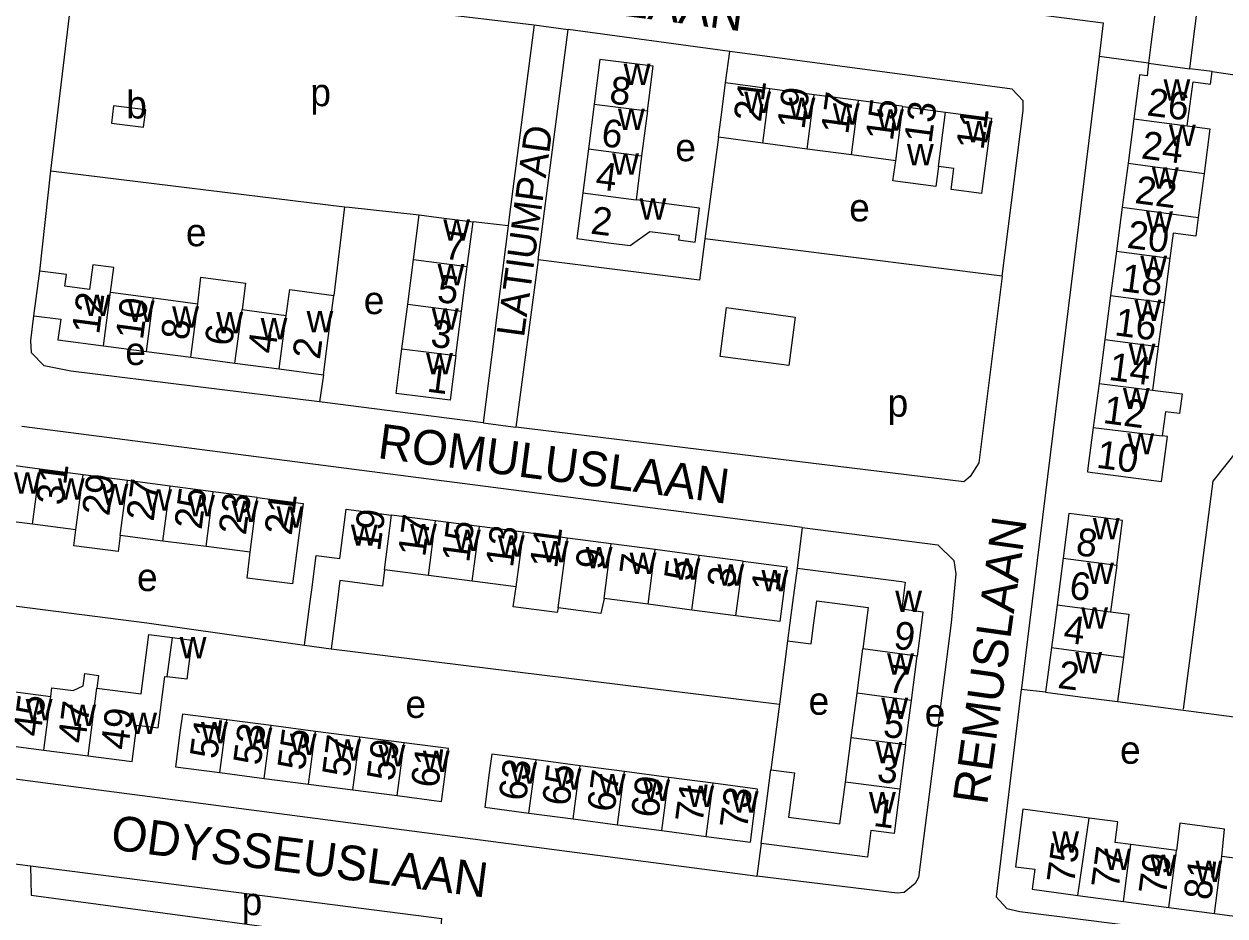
# Model space of a CAD drawing. Extents: x 161773 to 163836, y 384796 to 386521.
# Drawn here: x 162373.5 to 162546.6, y 386124.5 to 386253 of the extents above; entities that cross this region are included whole.
import ezdxf

# ---------------------------------------------------------------- set-up
doc = ezdxf.new("R2010")
doc.units = 0
for name, color, linetype in [('BLT_Basislijn', 7, 'Continuous'), ('BLT_Bebouwing', 7, 'Continuous'), ('BLT_Centroide', 7, 'Continuous'), ('BLT_Huisnummer', 7, 'Continuous'), ('BLT_Huisnummer_ tussenligend', 7, 'Continuous'), ('BLT_Onderverdeling_panden', 7, 'Continuous'), ('BLT_Straatnaam', 7, 'Continuous'), ('BLT_Straatnaam_verkleind', 7, 'Continuous')]:
    doc.layers.add(name, color=color, linetype=linetype)

msp = doc.modelspace()

# ---------------------------------------------------------------- linework, layer by layer
at = {"layer": 'BLT_Basislijn'}
for p, q in [((162447.05, 386252.85), (162451.93, 386252.19)), ((162447.64, 386218.99), (162451.93, 386252.19)), ((162475.24, 386249.02), (162451.93, 386252.19)), ((162474.65, 386244.47), (162475.24, 386249.02)), ((162535.6, 386247.3), (162528.49, 386248.27)), ((162544.76, 386246.1), (162549.69, 386245.41)), ((162473.62, 386236.64), (162471.67, 386222.02)), ((162377.35, 386231.82), (162419.71, 386226.64)), ((162419.71, 386226.64), (162418.17, 386213.85)), ((162443.28, 386223.88), (162438.24, 386224.45)), ((162443.28, 386223.88), (162439.7, 386195.48)), ((162514.5, 386216.65), (162471.67, 386222.02)), ((162447.64, 386218.99), (162444.41, 386194.89)), ((162416.67, 386202.42), (162416.09, 386198.52)), ((162439.7, 386195.48), (162444.41, 386194.89)), ((162485.66, 386180.43), (162484.94, 386174.58)), ((162417.76, 386162.95), (162482.39, 386154.98)), ((162483.57, 386164.09), (162482.39, 386154.98)), ((162520.78, 386156.68), (162517.27, 386157.06)), ((162482.39, 386154.98), (162481.17, 386145.49)), ((162531.15, 386155.33), (162553.03, 386152.48)), ((162479.79, 386134.91), (162479.16, 386130.19)), ((162369.94, 386132.24), (162374.45, 386131.66)), ((162374.45, 386131.66), (162433.75, 386124.08))]:
    msp.add_line(p, q, dxfattribs=at)
for points in [[(162407.16, 386268.86), (162529.09, 386253.11), (162528.49, 386248.27)], [(162377.35, 386231.82), (162380.53, 386258.21), (162382.19, 386260.12), (162383.56, 386260.45), (162447.05, 386252.85)], [(162447.05, 386252.85), (162443.49, 386225.52), (162443.28, 386223.88)], [(162514.5, 386216.65), (162517.54, 386240.51), (162517.56, 386241.89), (162515.97, 386243.59), (162475.24, 386249.02)], [(162528.49, 386248.27), (162518.46, 386166.67), (162517.3, 386157.29), (162517.27, 386157.06)], [(162540.64, 386154.24), (162544.92, 386187.1), (162550.17, 386193.67), (162555.68, 386244.61)], [(162375.77, 386217.37), (162377.35, 386231.82)], [(162419.71, 386226.64), (162420.4, 386226.55), (162430.47, 386225.45)], [(162471.67, 386222.02), (162470.87, 386216.06), (162447.64, 386218.99)], [(162514.5, 386216.65), (162511.13, 386189.75), (162509.9, 386187.78), (162508.97, 386186.98), (162444.41, 386194.89)], [(162416.09, 386198.52), (162380.25, 386202.96), (162376.4, 386203.69), (162374.56, 386205.6), (162374.49, 386207.35), (162374.92, 386210.93)], [(162439.7, 386195.48), (162416.85, 386198.43), (162416.09, 386198.52)], [(162485.66, 386180.43), (162484.59, 386180.57), (162373.17, 386194.96)], [(162485.66, 386180.43), (162505.24, 386177.91), (162507.54, 386175.68), (162507.82, 386173.74), (162507.16, 386166.67), (162502.44, 386130), (162501.96, 386129.11), (162500.37, 386127.81), (162499.36, 386127.73), (162479.16, 386130.19)], [(162349.54, 386172.01), (162391.2, 386166.67), (162413.94, 386163.45)], [(162517.27, 386157.06), (162513.65, 386127.2), (162515.18, 386125.55), (162517.05, 386125.1), (162553.21, 386120.54), (162557.19, 386120.68), (162558.62, 386122.04), (162567.26, 386150.66)], [(162346.48, 386147.55), (162478.17, 386130.31), (162479.16, 386130.19)], [(162374.45, 386131.66), (162374.52, 386127.46), (162431.78, 386119.74), (162433.18, 386119.69), (162433.34, 386119.94), (162433.75, 386124.08)]]:
    msp.add_lwpolyline(points, dxfattribs=at)
msp.add_lwpolyline([(162474.78, 386212.11), (162484.69, 386210.73), (162483.77, 386203.75), (162473.86, 386205.07)], close=True, dxfattribs=at)
at = {"layer": 'BLT_Bebouwing'}
for p, q in [((162481.04, 386243.63), (162474.65, 386244.47)), ((162487.43, 386242.78), (162481.04, 386243.63)), ((162493.81, 386241.94), (162487.43, 386242.78)), ((162455.69, 386241.42), (162454.86, 386234.96)), ((162500.2, 386241.09), (162506.35, 386240.28)), ((162463.38, 386240.43), (162462.54, 386233.97)), ((162533.49, 386239.28), (162532.66, 386232.93)), ((162480, 386235.79), (162473.62, 386236.64)), ((162486.39, 386234.95), (162480, 386235.79)), ((162454.86, 386234.96), (162454.04, 386228.63)), ((162462.54, 386233.97), (162461.73, 386227.64)), ((162492.78, 386234.1), (162486.39, 386234.95)), ((162499.16, 386233.26), (162492.78, 386234.1)), ((162532.66, 386232.93), (162531.82, 386226.58)), ((162543.63, 386231.44), (162542.76, 386225.07)), ((162429.64, 386219.02), (162430.47, 386225.45)), ((162531.82, 386226.58), (162530.98, 386220.22)), ((162437.41, 386218.03), (162438.24, 386224.45)), ((162530.98, 386220.22), (162530.14, 386213.87)), ((162428.82, 386212.6), (162429.64, 386219.02)), ((162436.59, 386211.6), (162437.41, 386218.03)), ((162538.69, 386219.21), (162537.85, 386212.85)), ((162374.92, 386210.93), (162375.77, 386217.37)), ((162385.99, 386214.31), (162392.17, 386213.49)), ((162392.17, 386213.49), (162398.55, 386212.65)), ((162530.14, 386213.87), (162529.31, 386207.51)), ((162537.85, 386212.85), (162537.02, 386206.5)), ((162404.93, 386211.81), (162411.31, 386210.97)), ((162427.99, 386206.18), (162428.82, 386212.6)), ((162435.76, 386205.18), (162436.59, 386211.6)), ((162384.98, 386206.6), (162391.15, 386205.78)), ((162529.31, 386207.51), (162528.47, 386201.16)), ((162537.02, 386206.5), (162536.19, 386200.22)), ((162391.15, 386205.78), (162397.53, 386204.94)), ((162397.53, 386204.94), (162403.91, 386204.1)), ((162403.91, 386204.1), (162410.29, 386203.26)), ((162410.29, 386203.26), (162416.67, 386202.42)), ((162528.47, 386201.16), (162527.63, 386194.81)), ((162375.77, 386188.82), (162369.41, 386189.65)), ((162382.02, 386188), (162375.77, 386188.82)), ((162388.4, 386187.17), (162382.02, 386188)), ((162394.57, 386186.37), (162388.4, 386187.17)), ((162400.79, 386185.56), (162394.57, 386186.37)), ((162407.13, 386184.73), (162400.79, 386185.56)), ((162374.73, 386180.89), (162368.37, 386181.71)), ((162432.83, 386181.39), (162426.5, 386182.22)), ((162380.98, 386180.09), (162374.73, 386180.89)), ((162439.16, 386180.56), (162432.83, 386181.39)), ((162445.5, 386179.73), (162439.16, 386180.56)), ((162393.53, 386178.47), (162387.37, 386179.27)), ((162399.75, 386177.67), (162393.53, 386178.47)), ((162451.83, 386178.9), (162445.5, 386179.73)), ((162458.16, 386178.07), (162451.83, 386178.9)), ((162406.12, 386176.85), (162399.75, 386177.67)), ((162464.49, 386177.24), (162458.16, 386178.07)), ((162470.82, 386176.41), (162464.49, 386177.24)), ((162477.16, 386175.58), (162470.82, 386176.41)), ((162523.3, 386176.01), (162522.42, 386169.28)), ((162531.02, 386175.01), (162530.14, 386168.27)), ((162431.8, 386173.51), (162425.47, 386174.34)), ((162438.13, 386172.68), (162431.8, 386173.51)), ((162444.46, 386171.85), (162438.13, 386172.68)), ((162463.46, 386169.36), (162457.13, 386170.19)), ((162469.79, 386168.53), (162463.46, 386169.36)), ((162476.12, 386167.7), (162469.79, 386168.53)), ((162413.94, 386163.45), (162417.76, 386162.95)), ((162493.59, 386156.53), (162494.42, 386162.92)), ((162521.62, 386163.12), (162520.78, 386156.68)), ((162501.42, 386155.51), (162502.25, 386161.9)), ((162531.99, 386161.73), (162531.15, 386155.33)), ((162371.15, 386156.89), (162377.35, 386156.08)), ((162492.76, 386150.14), (162493.59, 386156.53)), ((162500.59, 386149.12), (162501.42, 386155.51)), ((162402.73, 386152.71), (162396.33, 386153.54)), ((162409.12, 386151.88), (162402.73, 386152.71)), ((162415.51, 386151.05), (162409.12, 386151.88)), ((162421.9, 386150.23), (162415.51, 386151.05)), ((162370.14, 386149.17), (162376.34, 386148.36)), ((162428.3, 386149.4), (162421.9, 386150.23)), ((162491.92, 386143.75), (162492.76, 386150.14)), ((162376.34, 386148.36), (162382.73, 386147.53)), ((162453.69, 386146.09), (162447.31, 386146.93)), ((162460.08, 386145.25), (162453.69, 386146.09)), ((162401.74, 386145.1), (162408.14, 386144.27)), ((162408.14, 386144.27), (162414.53, 386143.45)), ((162466.46, 386144.41), (162460.08, 386145.25)), ((162472.84, 386143.57), (162466.46, 386144.41)), ((162414.53, 386143.45), (162420.92, 386142.62)), ((162420.92, 386142.62), (162427.31, 386141.79)), ((162446.3, 386139.27), (162452.69, 386138.43)), ((162452.69, 386138.43), (162459.07, 386137.59)), ((162459.07, 386137.59), (162465.45, 386136.75)), ((162465.45, 386136.75), (162471.83, 386135.91)), ((162539.63, 386133.89), (162533.07, 386134.76)), ((162525.42, 386127.42), (162531.98, 386126.55)), ((162531.98, 386126.55), (162538.55, 386125.69)), ((162538.55, 386125.69), (162545.11, 386124.82))]:
    msp.add_line(p, q, dxfattribs=at)
for points in [[(162541.54, 386246.52), (162541.98, 386250), (162544.33, 386268.51), (162539.75, 386269.09)], [(162536.59, 386255.14), (162535.94, 386250), (162535.6, 386247.3)], [(162463.38, 386240.43), (162463.57, 386241.92), (162464.21, 386246.88), (162456.53, 386247.87), (162455.69, 386241.42)], [(162535.6, 386247.3), (162535.39, 386245.5), (162534.33, 386245.64), (162534.27, 386245.14), (162533.49, 386239.28)], [(162541.2, 386238.27), (162542.04, 386244.62), (162544.52, 386244.29), (162544.76, 386246.1)], [(162544.76, 386246.1), (162541.54, 386246.52)], [(162473.62, 386236.64), (162474, 386239.52), (162474.65, 386244.47)], [(162390.75, 386238.11), (162391.06, 386240.61), (162386.42, 386241.19), (162386.11, 386238.69), (162390.75, 386238.11)], [(162500.2, 386241.09), (162500, 386241.12), (162493.81, 386241.94)], [(162506.35, 386240.28), (162512.97, 386239.4), (162511.54, 386228.52), (162507.15, 386229.1), (162507.56, 386232.15), (162505.32, 386232.44)], [(162541.2, 386238.27), (162544.43, 386237.86), (162543.63, 386231.44)], [(162505.32, 386232.44), (162504.94, 386229.57), (162498.74, 386230.37), (162499.16, 386233.26)], [(162454.04, 386228.63), (162453.19, 386222.04), (162458.15, 386221.4), (162460.88, 386221.05), (162463.71, 386223.07), (162467.95, 386222.52), (162467.86, 386221.87), (162470.27, 386221.55), (162470.9, 386226.45), (162461.73, 386227.64)], [(162430.47, 386225.45), (162433.28, 386225.09), (162438.24, 386224.45)], [(162542.76, 386225.07), (162542.41, 386222.41), (162539.17, 386222.84), (162538.69, 386219.21)], [(162385.99, 386214.31), (162386.46, 386217.86), (162383.42, 386218.26), (162382.95, 386214.71), (162379.41, 386215.18), (162379.64, 386216.86), (162375.77, 386217.37)], [(162398.55, 386212.65), (162398.97, 386216.49), (162405.42, 386215.64), (162404.93, 386211.81)], [(162411.31, 386210.97), (162411.8, 386214.69), (162418.17, 386213.85)], [(162416.67, 386202.42), (162417.32, 386207.38), (162418.17, 386213.85)], [(162374.92, 386210.93), (162378.79, 386210.42), (162378.4, 386207.47), (162384.98, 386206.6)], [(162435.76, 386205.18), (162434.93, 386198.76), (162427.17, 386199.75), (162427.8, 386204.71), (162427.99, 386206.18)], [(162536.19, 386200.22), (162540.45, 386199.66), (162540.07, 386196.84), (162538.05, 386197.1), (162537.59, 386193.61)], [(162527.63, 386194.81), (162526.86, 386188.95), (162526.79, 386188.45), (162537.48, 386187.04), (162538.33, 386193.51), (162537.59, 386193.61)], [(162407.13, 386184.73), (162413.73, 386183.87), (162413.08, 386178.92), (162412.22, 386172.29), (162405.66, 386173.14), (162406.12, 386176.85)], [(162413.94, 386163.45), (162414.76, 386169.74), (162414.99, 386171.45), (162415.64, 386176.41), (162419.01, 386175.97), (162419.94, 386183.08), (162426.5, 386182.22)], [(162531.02, 386175.01), (162531.86, 386181.45), (162529.1, 386181.81), (162524.14, 386182.46), (162523.3, 386176.01)], [(162387.37, 386179.27), (162387.06, 386176.94), (162380.67, 386177.76), (162380.98, 386180.09)], [(162477.16, 386175.58), (162483.49, 386174.75), (162482.84, 386169.79), (162482.46, 386166.87), (162476.12, 386167.7)], [(162425.47, 386174.34), (162425.16, 386171.97), (162419.05, 386172.77), (162418.59, 386169.24), (162417.76, 386162.95)], [(162484.94, 386174.58), (162484.29, 386169.63), (162483.9, 386166.67), (162483.57, 386164.09)], [(162484.94, 386174.58), (162500, 386172.62), (162500.55, 386172.55), (162500.04, 386168.69), (162503.08, 386168.29), (162502.87, 386166.67), (162502.25, 386161.9)], [(162450.51, 386168.85), (162450.36, 386168.16), (162444.04, 386168.98), (162444.46, 386171.85)], [(162457.13, 386170.19), (162456.65, 386168.05), (162450.51, 386168.85)], [(162483.57, 386164.09), (162486.98, 386163.65), (162487.37, 386166.67), (162487.79, 386169.84), (162495.2, 386168.88), (162494.91, 386166.67), (162494.42, 386162.92)], [(162522.42, 386169.28), (162522.08, 386166.67), (162521.62, 386163.12)], [(162530.14, 386168.27), (162532.79, 386167.92), (162531.99, 386161.73)], [(162384.02, 386157.28), (162390.37, 386156.45), (162391.49, 386165.01), (162394.9, 386164.57)], [(162394.9, 386164.57), (162397.71, 386164.21), (162396.98, 386158.55), (162394.16, 386158.9)], [(162377.35, 386156.08), (162377.52, 386157.34), (162380.6, 386156.94), (162382.02, 386157.62), (162382.25, 386159.37), (162384.26, 386159.11), (162384.02, 386157.28)], [(162392.86, 386151.56), (162393.82, 386158.94), (162394.16, 386158.9)], [(162520.78, 386156.68), (162525.74, 386156.03), (162531.15, 386155.33)], [(162396.33, 386153.54), (162395.99, 386150.89), (162395.35, 386145.93), (162401.74, 386145.1)], [(162382.73, 386147.53), (162389.1, 386146.7), (162389.79, 386151.96), (162392.86, 386151.56)], [(162427.31, 386141.79), (162433.7, 386140.96), (162434.34, 386145.92), (162434.69, 386148.57), (162428.3, 386149.4)], [(162500.59, 386149.12), (162500, 386144.64), (162499.75, 386142.73)], [(162447.31, 386146.93), (162440.93, 386147.77), (162440.57, 386145.07), (162439.92, 386140.11), (162446.3, 386139.27)], [(162479.79, 386134.91), (162480.44, 386139.87), (162481.17, 386145.49)], [(162481.17, 386145.49), (162484.55, 386145.05), (162483.72, 386138.67), (162491.13, 386137.71), (162491.92, 386143.75)], [(162471.83, 386135.91), (162478.22, 386135.07), (162478.87, 386140.03), (162479.23, 386142.73), (162472.84, 386143.57)], [(162499.75, 386142.73), (162498.92, 386136.34), (162495.58, 386136.78), (162495.08, 386132.92), (162479.79, 386134.91)], [(162527.04, 386138.56), (162517.5, 386139.82), (162516.41, 386131.55), (162519.24, 386131.18), (162518.85, 386128.29), (162525.42, 386127.42)], [(162533.07, 386134.76), (162530.81, 386135.05), (162531.2, 386138.01), (162527.04, 386138.56)], [(162546.19, 386133.02), (162546.58, 386136.96), (162540.13, 386137.81), (162539.63, 386133.89)], [(162545.11, 386124.82), (162551.67, 386123.95), (162552.14, 386127.49), (162556.35, 386126.93), (162557.42, 386134.97), (162552.83, 386135.57), (162552.39, 386132.2), (162546.19, 386133.02)]]:
    msp.add_lwpolyline(points, dxfattribs=at)
at = {"layer": 'BLT_Onderverdeling_panden'}
for p, q in [((162480, 386235.79), (162481.04, 386243.63)), ((162486.39, 386234.95), (162487.43, 386242.78)), ((162455.69, 386241.42), (162463.38, 386240.43)), ((162492.78, 386234.1), (162493.81, 386241.94)), ((162499.16, 386233.26), (162500.2, 386241.09)), ((162505.32, 386232.44), (162506.35, 386240.28)), ((162533.49, 386239.28), (162541.2, 386238.27)), ((162454.86, 386234.96), (162462.54, 386233.97)), ((162532.66, 386232.93), (162543.63, 386231.44)), ((162454.04, 386228.63), (162461.73, 386227.64)), ((162531.82, 386226.58), (162542.76, 386225.07)), ((162530.98, 386220.22), (162538.69, 386219.21)), ((162429.64, 386219.02), (162437.41, 386218.03)), ((162384.98, 386206.6), (162385.99, 386214.31)), ((162391.15, 386205.78), (162392.17, 386213.49)), ((162530.14, 386213.87), (162537.85, 386212.85)), ((162397.53, 386204.94), (162398.55, 386212.65)), ((162403.91, 386204.1), (162404.93, 386211.81)), ((162428.82, 386212.6), (162436.59, 386211.6)), ((162410.29, 386203.26), (162411.31, 386210.97)), ((162427.99, 386206.18), (162435.76, 386205.18)), ((162529.31, 386207.51), (162537.02, 386206.5)), ((162528.47, 386201.16), (162536.19, 386200.22)), ((162527.63, 386194.81), (162537.59, 386193.61)), ((162374.73, 386180.89), (162375.77, 386188.82)), ((162380.98, 386180.09), (162382.02, 386188)), ((162387.37, 386179.27), (162388.4, 386187.17)), ((162393.53, 386178.47), (162394.57, 386186.37)), ((162399.75, 386177.67), (162400.79, 386185.56)), ((162406.12, 386176.85), (162407.13, 386184.73)), ((162425.47, 386174.34), (162426.5, 386182.22)), ((162431.8, 386173.51), (162432.83, 386181.39)), ((162438.13, 386172.68), (162439.16, 386180.56)), ((162444.46, 386171.85), (162445.5, 386179.73)), ((162450.51, 386168.85), (162451.83, 386178.9)), ((162457.13, 386170.19), (162458.16, 386178.07)), ((162463.46, 386169.36), (162464.49, 386177.24)), ((162469.79, 386168.53), (162470.82, 386176.41)), ((162476.12, 386167.7), (162477.16, 386175.58)), ((162523.3, 386176.01), (162531.02, 386175.01)), ((162522.42, 386169.28), (162530.14, 386168.27)), ((162394.16, 386158.9), (162394.9, 386164.57)), ((162502.25, 386161.9), (162494.42, 386162.92)), ((162521.62, 386163.12), (162531.99, 386161.73)), ((162376.34, 386148.36), (162377.35, 386156.08)), ((162382.73, 386147.53), (162384.02, 386157.28)), ((162501.42, 386155.51), (162493.59, 386156.53)), ((162401.74, 386145.1), (162402.73, 386152.71)), ((162408.14, 386144.27), (162409.12, 386151.88)), ((162414.53, 386143.45), (162415.51, 386151.05)), ((162420.92, 386142.62), (162421.9, 386150.23)), ((162427.31, 386141.79), (162428.3, 386149.4)), ((162500.59, 386149.12), (162492.76, 386150.14)), ((162446.3, 386139.27), (162447.31, 386146.93)), ((162452.69, 386138.43), (162453.69, 386146.09)), ((162459.07, 386137.59), (162460.08, 386145.25)), ((162465.45, 386136.75), (162466.46, 386144.41)), ((162471.83, 386135.91), (162472.84, 386143.57)), ((162499.75, 386142.73), (162491.92, 386143.75)), ((162525.42, 386127.42), (162527.04, 386138.56)), ((162531.98, 386126.55), (162533.07, 386134.76)), ((162538.55, 386125.69), (162539.63, 386133.89)), ((162545.11, 386124.82), (162546.19, 386133.02))]:
    msp.add_line(p, q, dxfattribs=at)
msp.add_lwpolyline([(162535.6, 386247.3), (162541.54, 386246.52)], dxfattribs=at)

# ---------------------------------------------------------------- texts
at = {"layer": 'BLT_Centroide'}
for s, p in [('w', (162459.95, 386244.16)), ('p', (162414.78, 386241.12)), ('w', (162537.77, 386241.94)), ('b', (162388.24, 386239.35)), ('w', (162477.33, 386240.14)), ('w', (162483.72, 386239.3)), ('w', (162459.12, 386237.69)), ('w', (162490.11, 386238.45)), ('w', (162496.48, 386237.61)), ('w', (162509.27, 386235.91)), ('w', (162538.55, 386235.38)), ('e', (162467.39, 386233.19)), ('w', (162500.78, 386232.6)), ('w', (162458.28, 386231.25)), ('w', (162536.09, 386229.25)), ('w', (162462.23, 386224.78)), ('e', (162492.46, 386224.52)), ('w', (162535.25, 386222.88)), ('e', (162396.84, 386220.94)), ('w', (162433.94, 386221.75)), ('w', (162433.12, 386215.31)), ('w', (162534.42, 386216.53)), ('w', (162382.09, 386210.89)), ('w', (162388.47, 386210.05)), ('e', (162422.48, 386211.16)), ('w', (162533.58, 386210.19)), ('w', (162394.86, 386209.2)), ('w', (162401.23, 386208.39)), ('w', (162414.23, 386208.56)), ('w', (162432.29, 386208.91)), ('w', (162407.61, 386207.55)), ('e', (162388.1, 386203.83)), ('w', (162532.74, 386203.84)), ('w', (162431.46, 386202.47)), ('p', (162497.99, 386196.38)), ('w', (162531.91, 386197.47)), ('w', (162532.55, 386190.94)), ('w', (162372.06, 386185.28)), ('w', (162378.38, 386184.45)), ('w', (162384.69, 386183.64)), ('w', (162390.97, 386182.83)), ('w', (162397.16, 386182.02)), ('w', (162403.44, 386181.2)), ('w', (162409.92, 386180.38)), ('w', (162527.58, 386178.72)), ('w', (162420.62, 386177.78)), ('w', (162429.16, 386177.86)), ('w', (162435.48, 386177.03)), ('w', (162441.81, 386176.2)), ('w', (162448.14, 386175.38)), ('w', (162454.48, 386174.55)), ('w', (162460.81, 386173.72)), ('w', (162467.14, 386172.89)), ('w', (162473.47, 386172.06)), ('w', (162526.74, 386172.28)), ('e', (162389.79, 386171.26)), ('w', (162479.81, 386171.22)), ('w', (162499.09, 386168.25)), ('w', (162525.9, 386165.84)), ('w', (162395.94, 386161.56)), ('w', (162497.92, 386159.22)), ('w', (162525.05, 386159.41)), ('w', (162373.75, 386152.62)), ('e', (162428.49, 386152.98)), ('e', (162486.6, 386153.44)), ('w', (162497.09, 386152.81)), ('w', (162380.03, 386151.8)), ('e', (162503.35, 386151.75)), ('w', (162388.81, 386150.67)), ('w', (162399.03, 386149.31)), ('w', (162405.44, 386148.5)), ('w', (162411.83, 386147.66)), ('w', (162418.22, 386146.84)), ('w', (162424.61, 386146.02)), ('w', (162496.25, 386146.44)), ('e', (162531.5, 386146.38)), ('w', (162431, 386145.19)), ('w', (162443.61, 386143.52)), ('w', (162450, 386142.67)), ('w', (162456.38, 386141.84)), ('w', (162462.77, 386141)), ('w', (162469.14, 386140.16)), ('w', (162475.53, 386139.33)), ('w', (162495.31, 386139.22)), ('w', (162521.72, 386133.58)), ('w', (162529.23, 386131.08)), ('w', (162535.81, 386130.23)), ('w', (162542.38, 386129.36)), ('p', (162404.88, 386124.57))]:
    msp.add_text(s, height=4, dxfattribs=at).set_placement(p)
at = {"layer": 'BLT_Huisnummer'}
for s, rotation, p in [('8', 352.6512, (162457.76, 386241.55)), ('21', 82.4605, (162479.73, 386238.74)), ('26', 352.4857, (162535.25, 386239.82)), ('15', 82.4667, (162498.74, 386236.02)), ('11', 82.4676, (162511.81, 386234.71)), ('22', 352.492, (162533.51, 386227.18)), ('2', 352.6462, (162455.06, 386222.78)), ('7', 352.6781, (162433.95, 386219.17)), ('18', 352.4911, (162531.48, 386214.5)), ('12', 82.4857, (162384.33, 386208.14)), ('6', 82.4838, (162403.48, 386206.45)), ('2', 82.4856, (162416.14, 386204.53)), ('14', 352.4891, (162529.75, 386201.7)), ('1', 352.6853, (162431.47, 386200.01)), ('10', 352.4856, (162527.97, 386189.05)), ('29', 82.6628, (162385.79, 386181.98)), ('25', 82.6649, (162399.1, 386180.03)), ('21', 82.5765, (162412.09, 386179.19)), ('19', 82.5341, (162424.83, 386176.9)), ('13', 82.5403, (162443.98, 386174.55)), ('8', 352.5784, (162525.01, 386176.47)), ('9', 82.5384, (162456.93, 386174.25)), ('5', 82.5365, (162469.7, 386172.59)), ('1', 82.5296, (162482.27, 386171.08)), ('9', 352.5708, (162498.73, 386163)), ('2', 352.578, (162522.4, 386157.32)), ('49', 82.6234, (162388.49, 386148.26)), ('5', 352.5708, (162497.21, 386150.3)), ('51', 82.6314, (162401.34, 386146.97)), ('55', 82.6314, (162413.97, 386145.32)), ('61', 82.6348, (162433.2, 386142.79)), ('63', 82.5034, (162445.85, 386140.9)), ('67', 82.5024, (162458.61, 386139.3)), ('73', 82.497, (162477.72, 386136.86)), ('1', 352.5712, (162495.83, 386137.44)), ('75', 82.4685, (162524.86, 386128.98)), ('79', 82.4676, (162538.11, 386127.35))]:
    msp.add_text(s, height=4, rotation=rotation, dxfattribs=at).set_placement(p)
at = {"layer": 'BLT_Huisnummer_ tussenligend'}
for s, rotation, p in [('19', 82.4667, (162486, 386237.68)), ('17', 82.4667, (162492.31, 386236.96)), ('13', 82.4676, (162504.31, 386235.65)), ('6', 352.6462, (162456.59, 386235.4)), ('24', 352.492, (162534.44, 386233.62)), ('4', 352.6462, (162455.76, 386229.21)), ('20', 352.4911, (162532.38, 386220.74)), ('5', 352.6853, (162432.93, 386212.93)), ('10', 82.4838, (162390.64, 386207.36)), ('16', 352.4891, (162530.59, 386208.13)), ('8', 82.4838, (162397.17, 386207.29)), ('3', 352.6853, (162431.98, 386206.5)), ('4', 82.4856, (162409.71, 386205.35)), ('12', 352.4856, (162528.93, 386195.49)), ('31', 82.6628, (162379.18, 386183.51)), ('27', 82.6649, (162392.19, 386181.21)), ('23', 82.5765, (162405.48, 386179.23)), ('17', 82.5403, (162431.34, 386176.09)), ('15', 82.5403, (162437.66, 386175.27)), ('11', 82.5384, (162450.34, 386174.43)), ('7', 82.5365, (162463.26, 386173.41)), ('3', 82.5296, (162475.9, 386171.59)), ('6', 352.578, (162524.05, 386170.19)), ('4', 352.578, (162523.22, 386163.88)), ('7', 352.5708, (162497.91, 386156.74)), ('45', 82.5848, (162375.87, 386150.17)), ('47', 82.5848, (162382.31, 386149.2)), ('53', 82.6314, (162407.6, 386146.05)), ('57', 82.6314, (162420.41, 386144.35)), ('59', 82.6314, (162426.84, 386143.77)), ('3', 352.5712, (162496.34, 386143.82)), ('65', 82.5034, (162452.11, 386140.18)), ('69', 82.5024, (162464.93, 386138.47)), ('71', 82.5024, (162471.31, 386137.73)), ('77', 82.4685, (162531.29, 386128.25)), ('81', 82.4676, (162544.61, 386126.61))]:
    msp.add_text(s, height=4, rotation=rotation, dxfattribs=at).set_placement(p)
at = {"layer": 'BLT_Straatnaam'}
for s, rotation, p in [('REMUSLAAN', 352.4964, (162435.69, 386257.34)), ('ROMULUSLAAN', 352.5377, (162424.35, 386190.44)), ('REMUSLAAN', 82.0339, (162512.32, 386140.34)), ('ODYSSEUSLAAN', 352.6639, (162385.85, 386134.07))]:
    msp.add_text(s, height=5, rotation=rotation, dxfattribs=at).set_placement(p)
at = {"layer": 'BLT_Straatnaam_verkleind'}
msp.add_text('LATIUMPAD', height=4, rotation=82.2039, dxfattribs=at).set_placement((162445.57, 386207.72))

doc.saveas('drawing.dxf')
